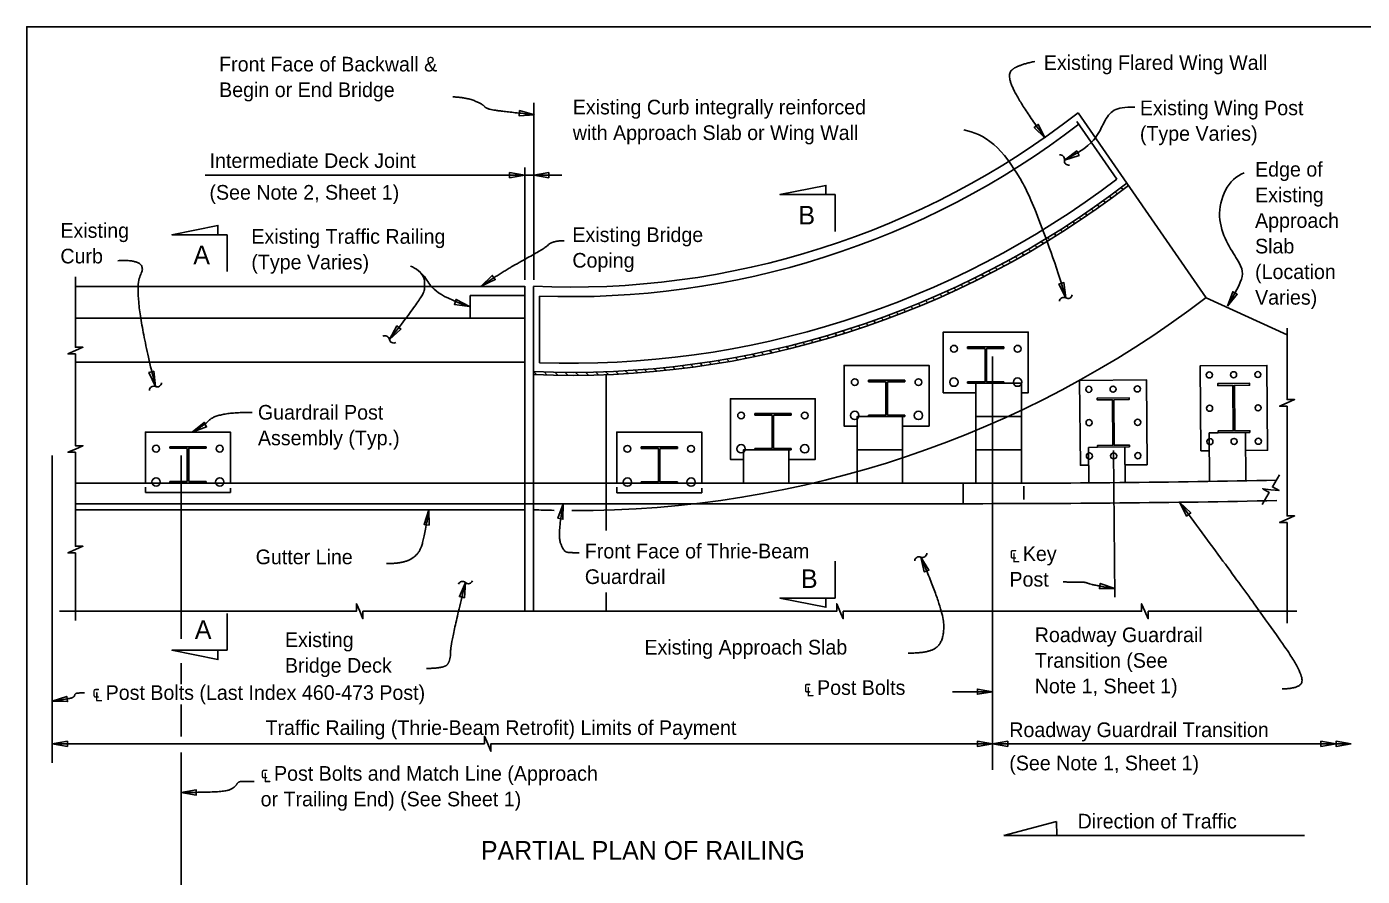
# Model space of a CAD drawing. Extents: x 0 to 41.1, y 0 to 25.9.
# Drawn here: x 0 to 18.36, y 14.27 to 25.95 of the extents above; entities that cross this region are included whole.
import ezdxf

# ---------------------------------------------------------------- set-up
doc = ezdxf.new("R2010")
doc.units = 0
for name, color, linetype in [('Dimension', 7, 'Continuous'), ('ExistSuperStruct', 7, 'Continuous'), ('Miscellaneous', 7, 'Continuous'), ('Miscellaneous1', 7, 'Continuous'), ('SteelMisc', 7, 'Continuous'), ('SteelMisc_h', 7, 'Continuous'), ('TextStructures', 7, 'Continuous')]:
    doc.layers.add(name, color=color, linetype=linetype)

msp = doc.modelspace()

# ---------------------------------------------------------------- linework, layer by layer
at = {"layer": 'Dimension'}
for p, q in [((6.968, 22.467), (6.968, 24.902)), ((7.353, 23.906), (2.454, 23.906)), ((6.846, 22.467), (6.846, 24.011)), ((10.353, 23.638), (10.985, 23.764)), ((10.985, 23.764), (10.985, 23.638)), ((11.112, 23.638), (10.353, 23.638)), ((11.112, 23.131), (11.112, 23.638)), ((1.996, 23.088), (2.629, 23.215)), ((2.629, 23.215), (2.629, 23.088)), ((2.755, 23.088), (1.996, 23.088)), ((2.755, 22.582), (2.755, 23.088)), ((13.276, 15.735), (13.276, 21.413)), ((2.122, 17.535), (2.122, 20.052)), ((14.939, 20.121), (14.955, 18.105)), ((11.112, 18.6), (11.112, 18.094)), ((11.112, 18.094), (10.353, 18.094)), ((10.353, 18.094), (10.985, 17.967)), ((10.985, 17.967), (10.985, 18.094)), ((2.755, 17.882), (2.755, 17.376)), ((2.755, 17.376), (1.996, 17.376)), ((1.996, 17.376), (2.629, 17.249)), ((2.629, 17.249), (2.629, 17.376)), ((2.122, 16.911), (2.122, 17.199)), ((12.726, 16.807), (13.276, 16.807)), ((2.122, 16.192), (2.122, 16.631)), ((2.122, 11.26), (2.122, 15.97)), ((13.432, 14.83), (14.154, 15.022)), ((14.154, 15.022), (14.156, 14.83)), ((17.562, 14.83), (13.432, 14.83)), ((14.156, 14.83), (17.369, 14.83)), ((17.369, 14.83), (17.562, 14.83))]:
    msp.add_line(p, q, dxfattribs=at)
for points in [[(6.977, 24.737), (6.774, 24.793), (6.767, 24.723)], [(13.998, 24.414), (13.904, 24.603), (13.847, 24.561)], [(13.998, 24.414), (13.995, 24.419), (13.993, 24.418)], [(14.263, 24.113), (14.464, 24.177), (14.432, 24.24)], [(6.846, 23.906), (6.637, 23.942), (6.637, 23.871)], [(6.968, 23.906), (7.176, 23.871), (7.176, 23.942)], [(10.985, 23.638), (10.985, 23.764), (10.353, 23.638)], [(2.629, 23.088), (2.629, 23.215), (1.996, 23.088)], [(6.248, 22.38), (6.439, 22.47), (6.399, 22.528)], [(14.28, 22.219), (14.255, 22.429), (14.187, 22.409)], [(16.504, 22.106), (16.638, 22.269), (16.577, 22.304)], [(6.088, 22.1), (5.901, 22.198), (5.879, 22.13)], [(4.986, 21.648), (5.143, 21.79), (5.088, 21.833)], [(1.77, 21.001), (1.747, 21.211), (1.679, 21.192)], [(2.274, 20.376), (2.473, 20.446), (2.439, 20.508)], [(5.528, 19.307), (5.461, 19.107), (5.531, 19.096)], [(7.373, 19.388), (7.3, 19.19), (7.369, 19.177)], [(15.847, 19.409), (15.942, 19.221), (15.999, 19.263)], [(12.289, 18.658), (12.335, 18.452), (12.4, 18.478)], [(6.031, 18.308), (5.947, 18.114), (6.015, 18.097)], [(14.955, 18.224), (14.756, 18.295), (14.743, 18.225)], [(10.985, 18.094), (10.985, 17.967), (10.353, 18.094)], [(2.629, 17.376), (2.629, 17.249), (1.996, 17.376)], [(0.351, 16.675), (0.562, 16.672), (0.551, 16.742)], [(13.276, 16.807), (13.067, 16.842), (13.067, 16.772)], [(0.351, 16.091), (0.559, 16.056), (0.559, 16.126)], [(0.351, 16.091), (0.559, 16.056), (0.559, 16.126)], [(13.276, 16.091), (13.067, 16.126), (13.067, 16.056)], [(13.275, 16.091), (13.484, 16.126), (13.484, 16.056)], [(17.997, 16.091), (17.788, 16.126), (17.788, 16.056)], [(18.205, 16.091), (17.997, 16.126), (17.997, 16.056)], [(2.123, 15.422), (2.331, 15.387), (2.331, 15.457)]]:
    msp.add_lwpolyline(points, close=True, dxfattribs=at)
for points in [[(0.669, 20.981), (0.669, 21.45), (0.566, 21.45), (0.669, 21.495), (0.773, 21.54), (0.669, 21.54), (0.669, 22.509)], [(17.323, 21.801), (17.323, 20.821), (17.426, 20.821), (17.323, 20.776), (17.22, 20.731), (17.323, 20.731), (17.323, 19.667)], [(0.669, 19.234), (0.669, 20.097), (0.566, 20.097), (0.669, 20.142), (0.773, 20.187), (0.669, 20.187), (0.669, 20.981)], [(0.669, 17.787), (0.669, 18.715), (0.566, 18.715), (0.669, 18.76), (0.773, 18.805), (0.669, 18.805), (0.669, 19.678)], [(17.218, 19.789), (17.122, 19.622), (17.212, 19.571), (17.1, 19.583), (16.988, 19.596), (17.077, 19.544), (16.981, 19.378)], [(17.323, 19.667), (17.323, 19.222), (17.426, 19.222), (17.323, 19.177), (17.22, 19.132), (17.323, 19.132), (17.323, 17.749)], [(0.451, 17.912), (4.532, 17.912), (4.532, 18.016), (4.577, 17.912), (4.622, 17.809), (4.622, 17.912), (6.853, 17.912)], [(6.853, 17.913), (11.133, 17.913), (11.133, 18.016), (11.178, 17.913), (11.223, 17.809), (11.223, 17.913), (13.488, 17.913)], [(13.488, 17.913), (15.324, 17.913), (15.324, 18.016), (15.369, 17.913), (15.414, 17.809), (15.414, 17.913), (17.458, 17.913)], [(0.351, 16.091), (6.291, 16.091), (6.291, 16.194), (6.336, 16.091), (6.381, 15.988), (6.381, 16.091), (18.205, 16.091)]]:
    msp.add_lwpolyline(points, dxfattribs=at)
for centre, start, end in [((14.204, 24.125), 349.2161, 100.9433), ((14.321, 24.103), 169.2161, 280.9433), ((14.252, 22.167), 60.6805, 172.4077), ((14.31, 22.271), 240.6805, 352.4077), ((4.926, 21.64), 8.6098, 120.3371), ((5.044, 21.658), 188.6098, 300.337), ((1.745, 20.946), 66.3072, 178.0344), ((1.793, 21.055), 246.3072, 358.0344), ((12.264, 18.603), 66.3072, 178.0344), ((12.312, 18.712), 246.3072, 358.0344), ((5.99, 18.264), 47.1839, 158.9112), ((6.071, 18.351), 227.1839, 338.9112)]:
    msp.add_arc(centre, 0.0596, start, end, dxfattribs=at)
for points, degree in [([(13.854, 25.468), (13.608, 25.418), (13.462, 25.277), (13.698, 24.826), (13.998, 24.414)], 2), ([(5.856, 24.982), (6.041, 24.975), (6.278, 24.876), (6.311, 24.817), (6.582, 24.777), (6.977, 24.737)], 2), ([(15.229, 24.842), (15.089, 24.842), (14.925, 24.823), (14.804, 24.64), (14.74, 24.474), (14.575, 24.273), (14.263, 24.113)], 3), ([(12.882, 24.527), (13.007, 24.504), (13.303, 24.389), (13.676, 23.853), (13.862, 23.445), (14.189, 22.552), (14.28, 22.219)], 3), ([(16.732, 23.937), (16.512, 23.858), (16.258, 23.304), (16.705, 22.67), (16.742, 22.497), (16.517, 22.127), (16.504, 22.106)], 3), ([(7.389, 23.005), (7.229, 23.005), (7.117, 22.897), (6.528, 22.574), (6.248, 22.38)], 2), ([(1.253, 22.73), (1.683, 22.756), (1.442, 22.304), (1.77, 21.001)], 2), ([(5.383, 22.598), (5.466, 22.505), (5.466, 22.408), (5.466, 22.254), (4.986, 21.648)], 2), ([(5.277, 22.655), (5.349, 22.63), (5.505, 22.513), (5.597, 22.259), (6.088, 22.1)], 3), ([(3.097, 20.645), (2.832, 20.645), (2.553, 20.588), (2.44, 20.468), (2.273, 20.376)], 2), ([(4.945, 18.568), (5.152, 18.568), (5.36, 18.666), (5.458, 18.862), (5.528, 19.307)], 2), ([(7.592, 18.716), (7.486, 18.716), (7.377, 18.73), (7.295, 18.974), (7.373, 19.388)], 2), ([(17.254, 16.846), (17.455, 16.846), (17.575, 16.982), (17.179, 17.609), (15.847, 19.409)], 2), ([(12.117, 17.337), (12.421, 17.337), (12.606, 17.507), (12.603, 17.931), (12.289, 18.658)], 2), ([(5.494, 17.127), (5.748, 17.127), (5.826, 17.247), (5.826, 17.48), (6.031, 18.308)], 2), ([(14.246, 18.315), (14.483, 18.313), (14.557, 18.31), (14.629, 18.278), (14.955, 18.224)], 2), ([(0.793, 16.791), (0.727, 16.79), (0.663, 16.784), (0.653, 16.727), (0.528, 16.703), (0.351, 16.675)], 2), ([(3.127, 15.574), (3.006, 15.574), (2.907, 15.574), (2.865, 15.493), (2.731, 15.433), (2.286, 15.422), (2.123, 15.422)], 2)]:
    msp.add_open_spline(points, degree=degree, dxfattribs=at)
at = {"layer": 'ExistSuperStruct'}
for p, q in [((14.981, 23.85), (14.431, 24.644)), ((16.209, 22.222), (14.45, 24.762)), ((6.846, 22.378), (0.669, 22.378)), ((6.096, 22.253), (6.846, 22.253)), ((6.846, 22.381), (6.846, 17.912)), ((6.966, 17.913), (6.966, 22.378)), ((7.049, 21.328), (7.049, 22.244)), ((16.21, 22.221), (17.323, 21.712)), ((0.669, 21.941), (6.846, 21.941)), ((0.669, 21.337), (6.846, 21.337)), ((7.966, 19.021), (7.966, 21.163)), ((0.669, 19.307), (6.846, 19.307)), ((7.966, 17.913), (7.966, 18.17))]:
    msp.add_line(p, q, dxfattribs=at)
msp.add_lwpolyline([(6.096, 22.253), (6.096, 21.941)], dxfattribs=at)
for centre, radius, start, end in [((7.48, 33.706), 11.339, 267.401, 307.9326), ((7.48, 33.706), 11.47, 267.8473, 307.4909), ((7.48, 33.706), 12.511, 267.6445, 307.6293), ((7.48, 33.706), 12.552, 267.6523, 307.6195), ((7.48, 33.706), 12.386, 268.0065, 307.273), ((7.546, 33.582), 14.286, 269.7804, 307.3301), ((7.546, 33.582), 14.286, 267.6736, 268.8059)]:
    msp.add_arc(centre, radius, start, end, dxfattribs=at)
at = {"layer": 'Miscellaneous'}
for p, q in [((15.04, 23.738), (15.07, 23.709)), ((14.714, 23.499), (14.743, 23.469)), ((14.796, 23.558), (14.826, 23.528)), ((14.878, 23.617), (14.908, 23.588)), ((14.959, 23.678), (14.989, 23.648)), ((14.463, 23.326), (14.492, 23.296)), ((14.547, 23.383), (14.577, 23.353)), ((14.631, 23.441), (14.66, 23.411)), ((14.206, 23.158), (14.236, 23.128)), ((14.292, 23.213), (14.322, 23.183)), ((14.378, 23.269), (14.407, 23.239)), ((13.944, 22.995), (13.975, 22.965)), ((14.032, 23.049), (14.062, 23.019)), ((14.12, 23.103), (14.15, 23.073)), ((13.587, 22.787), (13.617, 22.757)), ((13.677, 22.838), (13.707, 22.808)), ((13.767, 22.89), (13.797, 22.86)), ((13.856, 22.942), (13.886, 22.912)), ((13.219, 22.59), (13.249, 22.559)), ((13.312, 22.638), (13.342, 22.607)), ((13.404, 22.687), (13.434, 22.657)), ((13.496, 22.737), (13.526, 22.706)), ((12.84, 22.402), (12.871, 22.371)), ((12.936, 22.448), (12.967, 22.417)), ((13.031, 22.495), (13.062, 22.464)), ((13.125, 22.542), (13.156, 22.511)), ((12.451, 22.226), (12.483, 22.194)), ((12.55, 22.269), (12.581, 22.238)), ((12.647, 22.313), (12.678, 22.282)), ((12.744, 22.357), (12.775, 22.326)), ((12.051, 22.061), (12.083, 22.029)), ((12.152, 22.101), (12.184, 22.069)), ((12.252, 22.142), (12.284, 22.11)), ((12.352, 22.183), (12.384, 22.152)), ((11.534, 21.871), (11.566, 21.838)), ((11.639, 21.907), (11.671, 21.874)), ((11.743, 21.944), (11.775, 21.912)), ((11.846, 21.982), (11.878, 21.95)), ((11.949, 22.021), (11.981, 21.989)), ((10.887, 21.669), (10.92, 21.635)), ((10.997, 21.7), (11.031, 21.667)), ((11.106, 21.733), (11.139, 21.7)), ((11.214, 21.766), (11.247, 21.733)), ((11.321, 21.8), (11.354, 21.767)), ((11.428, 21.835), (11.461, 21.802)), ((10.21, 21.497), (10.244, 21.463)), ((10.325, 21.523), (10.36, 21.489)), ((10.439, 21.551), (10.473, 21.517)), ((10.553, 21.579), (10.587, 21.545)), ((10.665, 21.608), (10.699, 21.574)), ((10.777, 21.638), (10.81, 21.604)), ((9.13, 21.305), (9.166, 21.268)), ((9.254, 21.322), (9.29, 21.285)), ((9.377, 21.34), (9.413, 21.304)), ((9.499, 21.36), (9.535, 21.324)), ((9.62, 21.38), (9.656, 21.344)), ((9.74, 21.401), (9.775, 21.366)), ((9.859, 21.424), (9.894, 21.389)), ((9.977, 21.447), (10.012, 21.412)), ((10.094, 21.472), (10.129, 21.437)), ((6.966, 21.206), (6.966, 21.206)), ((6.966, 21.206), (7.009, 21.163)), ((7.112, 21.201), (7.155, 21.158)), ((7.257, 21.198), (7.299, 21.156)), ((7.4, 21.196), (7.442, 21.154)), ((7.542, 21.196), (7.583, 21.155)), ((7.682, 21.197), (7.722, 21.157)), ((7.82, 21.2), (7.86, 21.16)), ((7.957, 21.205), (7.997, 21.165)), ((8.092, 21.211), (8.132, 21.171)), ((8.227, 21.218), (8.265, 21.179)), ((8.359, 21.227), (8.398, 21.188)), ((8.491, 21.236), (8.529, 21.198)), ((8.621, 21.248), (8.659, 21.21)), ((8.75, 21.26), (8.788, 21.222)), ((8.878, 21.274), (8.915, 21.237)), ((9.004, 21.289), (9.041, 21.252)), ((13.432, 21.046), (13.505, 21.046)), ((16.25, 20.363), (16.375, 20.364)), ((16.25, 20.363), (16.256, 19.699)), ((16.75, 20.368), (16.756, 19.699)), ((0.351, 20.052), (0.351, 15.829)), ((14.594, 20.165), (14.719, 20.166)), ((14.594, 20.165), (14.598, 19.677)), ((15.094, 20.169), (15.098, 19.681)), ((12.871, 19.39), (12.871, 19.671)), ((13.704, 19.448), (13.704, 19.633))]:
    msp.add_line(p, q, dxfattribs=at)
for points in [[(13.671, 21.046), (13.671, 20.588), (13.046, 20.588), (13.046, 21.046)], [(12.037, 20.588), (12.037, 20.129), (11.412, 20.129), (11.412, 20.588)], [(13.671, 20.588), (13.671, 20.129), (13.046, 20.129), (13.046, 20.588)], [(10.475, 20.129), (10.475, 19.671), (9.85, 19.671), (9.85, 20.129)], [(12.037, 20.129), (12.037, 19.671), (11.412, 19.671), (11.412, 20.129)], [(13.671, 20.129), (13.671, 19.671), (13.046, 19.671), (13.046, 20.129)]]:
    msp.add_lwpolyline(points, close=True, dxfattribs=at)
for radius in [201.097, 201.377]:
    msp.add_arc((13.061, 220.768), radius, 269.94565, 271.17203, dxfattribs=at)
at = {"layer": 'Miscellaneous1'}
msp.add_lwpolyline([(0, 25.946), (41.051, 25.946), (41.051, 0), (0, 0)], close=True, dxfattribs=at)
at = {"layer": 'SteelMisc'}
for p, q in [((13.432, 21.546), (12.932, 21.546)), ((12.932, 21.546), (12.932, 21.525)), ((13.161, 21.525), (12.932, 21.525)), ((13.171, 21.515), (13.171, 21.067)), ((13.192, 21.515), (13.192, 21.067)), ((13.432, 21.525), (13.203, 21.525)), ((13.432, 21.546), (13.432, 21.525)), ((13.171, 21.067), (12.932, 21.067)), ((12.932, 21.046), (12.932, 21.067)), ((13.432, 21.046), (12.932, 21.046)), ((13.432, 21.067), (13.192, 21.067)), ((13.432, 21.046), (13.432, 21.067)), ((1.966, 20.173), (2.466, 20.173)), ((1.966, 20.173), (1.966, 20.152)), ((1.966, 20.152), (2.195, 20.152)), ((2.205, 20.142), (2.205, 19.694)), ((2.226, 20.142), (2.226, 19.694)), ((2.236, 20.152), (2.466, 20.152)), ((2.466, 20.173), (2.466, 20.152)), ((8.444, 20.171), (8.944, 20.171)), ((8.444, 20.171), (8.444, 20.15)), ((8.444, 20.15), (8.673, 20.15)), ((8.683, 20.14), (8.683, 19.692)), ((8.704, 20.14), (8.704, 19.692)), ((8.714, 20.15), (8.944, 20.15)), ((8.944, 20.171), (8.944, 20.15)), ((0.669, 19.671), (12.871, 19.671)), ((1.966, 19.694), (2.205, 19.694)), ((1.966, 19.673), (1.966, 19.694)), ((1.966, 19.673), (2.466, 19.673)), ((2.226, 19.694), (2.466, 19.694)), ((2.466, 19.673), (2.466, 19.694)), ((8.444, 19.692), (8.683, 19.692)), ((8.444, 19.671), (8.444, 19.692)), ((8.444, 19.671), (8.944, 19.671)), ((8.704, 19.692), (8.944, 19.692)), ((8.944, 19.671), (8.944, 19.692)), ((0.669, 19.39), (12.871, 19.39))]:
    msp.add_line(p, q, dxfattribs=at)
for points in [[(13.046, 20.916), (12.598, 20.916), (12.598, 21.749), (13.765, 21.749), (13.765, 20.916), (13.671, 20.916)], [(2.799, 19.671), (2.799, 20.376), (1.632, 20.376), (1.632, 19.671)], [(9.277, 19.671), (9.277, 20.374), (8.11, 20.374), (8.11, 19.671)], [(1.632, 19.543), (1.632, 19.62)], [(2.799, 19.605), (2.799, 19.543)], [(8.11, 19.541), (8.11, 19.618)], [(9.277, 19.602), (9.277, 19.541)]]:
    msp.add_lwpolyline(points, dxfattribs=at)
for centre, radius in [((12.744, 21.52), 0.0469), ((13.619, 21.52), 0.0469), ((12.744, 21.061), 0.0573), ((13.619, 21.061), 0.0573), ((1.778, 20.147), 0.0469), ((2.653, 20.147), 0.0469), ((8.256, 20.145), 0.0469), ((9.131, 20.145), 0.0469), ((1.778, 19.689), 0.0573), ((2.653, 19.689), 0.0573), ((8.256, 19.687), 0.0573), ((9.131, 19.687), 0.0573)]:
    msp.add_circle(centre, radius, dxfattribs=at)
for centre, start, end in [((13.161, 21.515), 0, 90), ((13.203, 21.515), 90, 180), ((2.195, 20.142), 0, 90), ((2.236, 20.142), 90, 180), ((8.673, 20.14), 0, 90), ((8.714, 20.14), 90, 180)]:
    msp.add_arc(centre, 0.0104, start, end, dxfattribs=at)
at = {"layer": 'SteelMisc_h'}
for p, q in [((11.569, 21.088), (12.069, 21.088)), ((11.569, 21.088), (11.569, 21.067)), ((11.569, 21.067), (11.798, 21.067)), ((11.808, 21.056), (11.808, 20.608)), ((11.829, 21.056), (11.829, 20.608)), ((11.839, 21.067), (12.069, 21.067)), ((12.069, 21.088), (12.069, 21.067)), ((10.006, 20.629), (10.506, 20.629)), ((10.006, 20.629), (10.006, 20.608)), ((10.006, 20.608), (10.235, 20.608)), ((10.246, 20.598), (10.246, 20.15)), ((10.266, 20.598), (10.266, 20.15)), ((10.277, 20.608), (10.506, 20.608)), ((10.506, 20.629), (10.506, 20.608)), ((11.569, 20.608), (11.808, 20.608)), ((11.569, 20.588), (11.569, 20.608)), ((11.569, 20.588), (12.069, 20.588)), ((11.829, 20.608), (12.069, 20.608)), ((12.069, 20.588), (12.069, 20.608)), ((10.006, 20.15), (10.246, 20.15)), ((10.006, 20.129), (10.006, 20.15)), ((10.006, 20.129), (10.506, 20.129)), ((10.266, 20.15), (10.506, 20.15)), ((10.506, 20.129), (10.506, 20.15))]:
    msp.add_line(p, q, dxfattribs=at)
for points in [[(12.037, 20.457), (12.402, 20.457), (12.402, 21.291), (11.235, 21.291), (11.235, 20.457), (11.412, 20.457)], [(16.752, 20.123), (17.054, 20.125), (17.045, 21.292), (16.128, 21.284), (16.138, 20.118), (16.252, 20.119)], [(15.096, 19.925), (15.399, 19.927), (15.389, 21.094), (14.472, 21.086), (14.482, 19.92), (14.596, 19.921)], [(16.813, 20.368), (16.375, 20.364), (16.375, 20.39), (16.583, 20.392), (16.578, 21.017), (16.37, 21.015), (16.37, 21.041), (16.807, 21.045), (16.807, 21.019), (16.599, 21.017), (16.604, 20.392), (16.813, 20.394), (16.813, 20.368)], [(10.475, 19.999), (10.839, 19.999), (10.839, 20.832), (9.673, 20.832), (9.673, 19.999), (9.85, 19.999)], [(15.157, 20.17), (14.719, 20.166), (14.719, 20.192), (14.928, 20.194), (14.922, 20.819), (14.714, 20.817), (14.714, 20.843), (15.151, 20.847), (15.151, 20.821), (14.943, 20.819), (14.948, 20.194), (15.157, 20.196), (15.157, 20.17)], [(1.632, 19.543), (2.799, 19.543)], [(8.11, 19.541), (9.277, 19.541)]]:
    msp.add_lwpolyline(points, dxfattribs=at)
for centre, radius in [((16.254, 21.16), 0.0417), ((16.587, 21.163), 0.0417), ((16.921, 21.166), 0.0417), ((11.381, 21.061), 0.0469), ((12.256, 21.061), 0.0469), ((14.598, 20.962), 0.0417), ((14.932, 20.965), 0.0417), ((15.265, 20.968), 0.0417), ((16.258, 20.702), 0.0417), ((16.925, 20.708), 0.0417), ((9.819, 20.603), 0.0469), ((10.694, 20.603), 0.0469), ((11.381, 20.603), 0.0573), ((12.256, 20.603), 0.0573), ((14.602, 20.504), 0.0417), ((15.269, 20.509), 0.0417), ((9.819, 20.145), 0.0573), ((10.694, 20.145), 0.0573), ((16.262, 20.244), 0.0417), ((16.595, 20.246), 0.0417), ((16.928, 20.249), 0.0417), ((14.606, 20.046), 0.0417), ((14.939, 20.048), 0.0417), ((15.272, 20.051), 0.0417)]:
    msp.add_circle(centre, radius, dxfattribs=at)
for centre, start, end in [((11.798, 21.056), 0, 90), ((11.839, 21.056), 90, 180), ((10.235, 20.598), 0, 90), ((10.277, 20.598), 90, 180)]:
    msp.add_arc(centre, 0.0104, start, end, dxfattribs=at)
at = {"layer": 'TextStructures'}
msp.add_lwpolyline([(0, 0), (41.051, 0), (41.051, 25.946), (0, 25.946)], close=True, dxfattribs=at)

# ---------------------------------------------------------------- texts
at = {"layer": 'Dimension'}
for s, p in [('Front Face of Backwall &', (2.645, 25.331)), ('Begin or End Bridge', (2.645, 24.979)), ('Existing Curb integrally reinforced ', (7.505, 24.741)), ('Existing Wing Post ', (15.3, 24.73)), ('with Approach Slab or Wing Wall', (7.505, 24.389)), ('(Type Varies)', (15.3, 24.378)), ('Edge of', (16.883, 23.886)), ('Existing', (16.883, 23.534)), ('Approach', (16.883, 23.182)), ('Existing ', (0.463, 23.045)), ('Existing Traffic Railing', (3.088, 22.963)), ('Existing Bridge ', (7.5, 22.987)), ('Slab ', (16.883, 22.83)), ('Curb', (0.463, 22.693)), ('(Type Varies)', (3.088, 22.611)), ('Coping ', (7.5, 22.635)), ('(Location', (16.883, 22.478)), ('Varies)', (16.883, 22.126)), ('Guardrail Post ', (3.178, 20.546)), ('Assembly (Typ.)', (3.178, 20.194)), ('Front Face of Thrie-Beam ', (7.671, 18.639)), ('℄ Key ', (13.507, 18.603)), ('Guardrail', (7.671, 18.287)), ('Post', (13.507, 18.251)), ('Existing ', (3.549, 17.42)), ('Roadway Guardrail ', (13.855, 17.488)), ('Bridge Deck', (3.549, 17.068)), ('Transition (See ', (13.855, 17.136)), ('Note 1, Sheet 1)', (13.855, 16.784)), ('Roadway Guardrail Transition', (13.505, 16.183)), ('℄ Post Bolts and Match Line (Approach ', (3.215, 15.583)), ('(See Note 1, Sheet 1)', (13.505, 15.726)), ('or Trailing End) (See Sheet 1)', (3.215, 15.231))]:
    msp.add_text(s, height=0.2016, dxfattribs=at).set_placement(p)
at = {"layer": 'TextStructures'}
for s, height, p in [('Existing Flared Wing Wall', 0.2016, (13.98, 25.352)), ('Intermediate Deck Joint', 0.2016, (2.514, 24.005)), ('(See Note 2, Sheet 1)', 0.2016, (2.512, 23.569)), ('B', 0.256, (10.607, 23.228)), ('A', 0.256, (2.29, 22.682)), ('Gutter Line', 0.2016, (3.147, 18.559)), ('B', 0.256, (10.642, 18.232)), ('A', 0.256, (2.311, 17.533)), ('Existing Approach Slab', 0.2016, (8.49, 17.318)), ('℄ Post Bolts (Last Index 460-473 Post)', 0.2016, (0.901, 16.694)), ('℄ Post Bolts', 0.2016, (10.679, 16.763)), ('Traffic Railing (Thrie-Beam Retrofit) Limits of Payment', 0.2016, (3.282, 16.212)), ('PARTIAL PLAN OF RAILING', 0.256, (6.243, 14.498))]:
    msp.add_text(s, height=height, dxfattribs=at).set_placement(p)
msp.add_text('Direction of Traffic', height=0.2016, rotation=359.9998, dxfattribs=at).set_placement((14.444, 14.927))

doc.saveas('drawing.dxf')
